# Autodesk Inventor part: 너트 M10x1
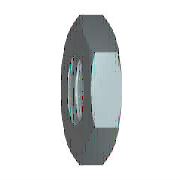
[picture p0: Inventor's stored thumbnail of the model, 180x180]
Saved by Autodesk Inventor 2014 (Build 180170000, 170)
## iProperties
Created: 2012-02
Part Number: 너트 M10x1
Material: 강철, 연강
Description: 6각 가는 너트 - 이중 모따기(부품 등급 A) - 정밀 나사산
Document SubType Name: Modeling
Standard: JIS B 1181
Designer: mduedu
Standards Organization: JIS
Language: ko-KR
Size Designation: M10x1
Categories: <MemberInstance><Categories><Category DisplayName="조임쇠" InternalName="e4da775c-781d-43d5-af7c-5136215cf5a6" Mnemonic="FSTN"><Category DisplayName="너트" InternalN
Density: 7.86 g/cm^3
Appearance: 강철
IsCustomPart: 1
Author: mduedu
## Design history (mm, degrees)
node "MSC_A1"
node "MSC_PT1"
node "MSC_PT2"
node "MSC_PF1"
body "Solid1"
sketch "스케치1"
  geometry: L1 (8, 4.619)-(8, -4.619); L2 (8, -4.619)-(0, -9.238); L3 (0, -9.238)-(-8, -4.619); L4 (-8, -4.619)-(-8, 4.619); L5 (-8, 4.619)-(0, 9.238); L6 (0, 9.238)-(8, 4.619); C1 r 8 at (0, 0); 2 further points
  constraints: 12 end point, 2 coincident, 1 centre point, 1 tangent, 1 vertical, 11 other
  dimensions: "d0" = 16 diameter of C1 (= ParS)
extrude "돌출1" new body sketch "스케치1" distance "d1" = 5 (= M); taper "d2" = 0 deg
sketch "스케치2"
  geometry: L1 (-8, 4.619)-(0, 9.238) reference; L2 (0, -9.238)-(-8, -4.619) reference; L3 (-8, 4.619)-(8, -4.619); L4 (-8, -4.619)-(8, 4.619); 1 further point
  constraints: 4 end point, 2 midpoint, 2 parallel
hole "구멍1" sketch "스케치2" diameter "d3" = 8.91747; stored, may be unused: countersink angle "d7" = 90 deg, drill point angle "d9" = 118 deg; dims "d4" = 6, "d5" = 4, "d6" = 2, "d8" = 8
chamfer "모따기1" distance "d10" = 0.5 (= 0.5 x PTC); stored, may be unused: second distance "d11" = 2, angle "d12" = 45 deg
revolve "회전1" stored, may be unused: angle "d15" = 90 deg
sketch "스케치3"
  geometry: L1 (-9.238, 5)-(-9.238, 4.285); L2 (-9.238, 4.285)-(-8, 5); L3 (-8, 5)-(-9.238, 5); L4 (-9.238, 0.715)-(-9.238, 0); L5 (-9.238, 0)-(-8, 0); L6 (-8, 0)-(-9.238, 0.715); L7 (0, 6)-(0, -1) reference; L8 (-4.619, 5)-(-9.238, 5) reference; L9 (-4.619, 0)-(-9.238, 0) reference; L10 (-9.238, 0)-(-9.238, 5) reference
  constraints: 12 end point, 4 collinear, 3 perpendicular, 2 equal length, 1 vertical
  dimensions: "d13" = 30 deg angle of L2 L3; "d14" = 8 distance from line of L2.end L7 (= 0.5 x ParS)
other parameters: "ParS" = 16 [user parameter; used in 2 equation terms], "M" = 5 [user parameter; used in 1 equation term], "PTC" = 1 [user parameter; used in 1 equation term], "d17" = 0, "d18" = 0, "d19" = 0, "d20" = 0, "d21" = 0, "d22" = 0, "d23" = 0
